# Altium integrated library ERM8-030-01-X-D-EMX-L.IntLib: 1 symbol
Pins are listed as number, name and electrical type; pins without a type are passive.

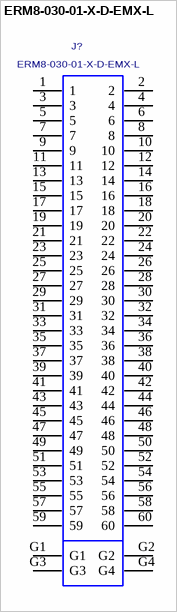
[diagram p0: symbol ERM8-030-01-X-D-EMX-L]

## ERM8-030-01-X-D-EMX-L
designator J?
0.8MM EDGE RATE TERMINAL ASSEMBLY.; MANUFACTURER: SAMTEC
footprint ERM8-030-01-X-D-EMX-L
pins: 1, 2, 3, 4, 5, 6, 7, 8, 9, 10, 11, 12, 13, 14, 15, 16, 17, 18, 19, 20, 21, 22, 23, 24, 25, 26, 27, 28, 29, 30, 31, 32, 33, 34, 35, 36, 37, 38, 39, 40, 41, 42, 43, 44, 45, 46, 47, 48, 49, 50, 51, 52, 53, 54, 55, 56, 57, 58, 59, 60, G1, G2, G3, G4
